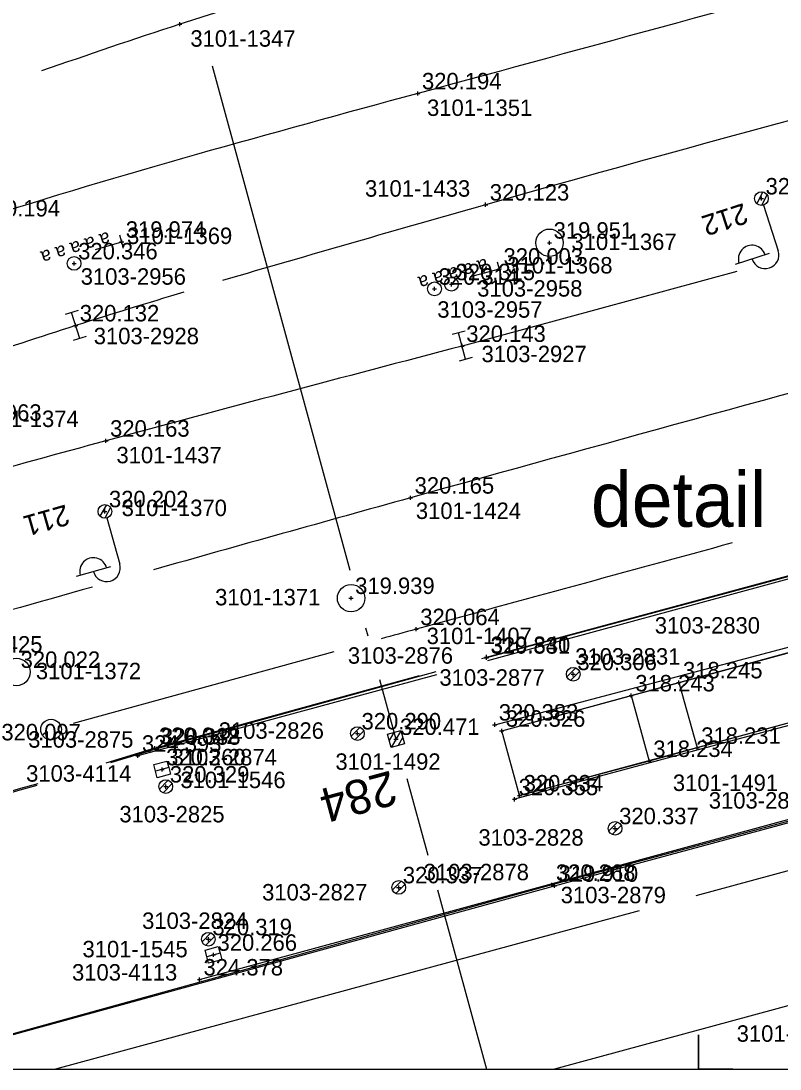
# Model space of a CAD drawing. Extents: x -821875 to -821475, y -1070280 to -1069975.
# Drawn here: x -821774.71 to -821747.03, y -1070250 to -1070211.76 of the extents above; entities that cross this region are included whole.
import ezdxf

# ---------------------------------------------------------------- set-up
doc = ezdxf.new("R2010")
doc.units = 0
for name, color, linetype in [('Vrstva 1', 7, 'Continuous'), ('Vrstva 11', 7, 'Continuous'), ('Vrstva 14', 7, 'Continuous'), ('Vrstva 17', 7, 'Continuous'), ('Vrstva 18', 7, 'Continuous'), ('Vrstva 25', 7, 'Continuous'), ('Vrstva 28', 7, 'Continuous'), ('Vrstva 3', 7, 'Continuous'), ('Vrstva 36', 7, 'Continuous'), ('Vrstva 43', 7, 'Continuous'), ('Vrstva 51', 7, 'Continuous'), ('Vrstva 6', 7, 'Continuous'), ('Vrstva 60', 7, 'Continuous'), ('Vrstva 61', 7, 'Continuous'), ('Vrstva 7', 7, 'Continuous')]:
    doc.layers.add(name, color=color, linetype=linetype)

# ---------------------------------------------------------------- blocks, each defined once
blk = doc.blocks.new('BOD')
at = {"layer": 'Vrstva 3'}
for p, q in [((-0.15, 0), (0.15, 0)), ((0, -0.15), (0, 0.15))]:
    blk.add_line(p, q, dxfattribs=at)

msp = doc.modelspace()

# ---------------------------------------------------------------- linework, layer by layer
at = {"layer": 'Vrstva 1'}
msp.add_line((-821763.295, -1070234.772), (-821772.807, -1070237.389), dxfattribs=at)
msp.add_lwpolyline([(-821500, -1070000), (-821850, -1070000), (-821850, -1070250), (-821500, -1070250)], close=True, dxfattribs=at)
msp.add_lwpolyline([(-821500, -1070000), (-821850, -1070000), (-821850, -1070250), (-821500, -1070250)], close=True, dxfattribs=at)
for points in [[(-821748.606, -1070220.895), (-821758.62, -1070223.618)], [(-821740.322, -1070241.025), (-821750.102, -1070243.674)], [(-821752.166, -1070244.233), (-821773.458, -1070250)], [(-821739.032, -1070245.599), (-821755.257, -1070250)], [(-821750, -1070250), (-821750, -1070248.75), (-821750, -1070250)], [(-821751.25, -1070250), (-821750, -1070250)], [(-821750, -1070250), (-821748.75, -1070250), (-821750, -1070250)]]:
    msp.add_lwpolyline(points, dxfattribs=at)
for points in [[(-821710.276, -1070200.761), (-821741.264, -1070209.238), (-821760.235, -1070214.402), (-821776.338, -1070219.041), (-821794.464, -1070225.772), (-821811.866, -1070233.595), (-821823.5, -1070239.204)], [(-821742.542, -1070204.561), (-821755.391, -1070207.946), (-821768.915, -1070211.875), (-821773.964, -1070213.578)], [(-821709.336, -1070205.287), (-821731.872, -1070211.395), (-821757.763, -1070218.461), (-821767.367, -1070221.229)], [(-821705.268, -1070214.096), (-821739.917, -1070223.49), (-821760.504, -1070229.155), (-821769.875, -1070231.779)], [(-821768.767, -1070221.652), (-821772.719, -1070222.87), (-821780.508, -1070225.552), (-821790.618, -1070229.47), (-821802.014, -1070234.586)], [(-821758.62, -1070223.618), (-821771.612, -1070227.076), (-821781.946, -1070229.982), (-821793.276, -1070233.523), (-821801.308, -1070236.276)], [(-821748.77, -1070230.804), (-821760.298, -1070233.952), (-821761.578, -1070234.302)], [(-821772.109, -1070232.413), (-821778.099, -1070234.122), (-821792.905, -1070238.705), (-821809.105, -1070244.426), (-821819.525, -1070248.451)]]:
    msp.add_spline(points, degree=3, dxfattribs=at)
at = {"layer": 'Vrstva 11'}
for p, q in [((-821767.74, -1070213.4), (-821762.717, -1070231.799)), ((-821762.144, -1070233.898), (-821762.063, -1070234.195)), ((-821761.629, -1070235.783), (-821761.035, -1070237.959)), ((-821761.113, -1070237.721), (-821761.28, -1070238.011)), ((-821760.859, -1070237.654), (-821761.21, -1070238.265)), ((-821760.79, -1070237.91), (-821760.954, -1070238.196)), ((-821761.035, -1070237.959), (-821761.029, -1070237.982)), ((-821760.639, -1070239.403), (-821759.871, -1070242.2)), ((-821759.525, -1070243.46), (-821757.731, -1070250))]:
    msp.add_line(p, q, dxfattribs=at)
msp.add_lwpolyline([(-821760.729, -1070238.135), (-821761.211, -1070238.265), (-821761.341, -1070237.783), (-821760.859, -1070237.653)], close=True, dxfattribs=at)
msp.add_lwpolyline([(-821760.729, -1070238.135), (-821761.211, -1070238.265), (-821761.341, -1070237.783), (-821760.859, -1070237.653), (-821760.729, -1070238.135)], dxfattribs=at)
at = {"layer": 'Vrstva 14'}
for p, q in [((-821664.962, -1070209.896), (-821757.694, -1070235.105)), ((-821768.204, -1070246.736), (-821665.012, -1070218.658)), ((-821729.033, -1070227.268), (-821757.732, -1070234.994)), ((-821757.728, -1070234.967), (-821729.11, -1070227.249)), ((-821757.901, -1070235.014), (-821757.728, -1070234.967)), ((-821757.732, -1070234.994), (-821757.743, -1070234.997)), ((-821759.554, -1070235.61), (-821770.449, -1070238.572)), ((-821759.581, -1070235.505), (-821769.755, -1070238.316)), ((-821769.828, -1070238.29), (-821760.173, -1070235.639)), ((-821727.507, -1070235.797), (-821755.35, -1070243.283)), ((-821755.252, -1070243.318), (-821727.465, -1070235.8)), ((-821769.828, -1070238.29), (-821771.614, -1070238.834)), ((-821769.755, -1070238.316), (-821771.448, -1070238.832)), ((-821755.35, -1070243.283), (-821779.667, -1070250)), ((-821779.579, -1070250), (-821755.252, -1070243.318))]:
    msp.add_line(p, q, dxfattribs=at)
for points in [[(-821774.103, -1070239.592), (-821793.856, -1070245.607), (-821805.756, -1070250)], [(-821774.135, -1070239.651), (-821793.856, -1070245.665), (-821805.638, -1070250)]]:
    msp.add_spline(points, degree=3, dxfattribs=at)
at = {"layer": 'Vrstva 17'}
msp.add_lwpolyline([(-821757.433, -1070237.436), (-821746.637, -1070234.581), (-821745.884, -1070237.251), (-821756.709, -1070240.158)], dxfattribs=at)
at = {"layer": 'Vrstva 18'}
for points in [[(-821757.178, -1070237.66), (-821746.762, -1070234.831), (-821746.658, -1070234.777), (-821746.001, -1070234.589)], [(-821756.527, -1070240.021), (-821746.098, -1070237.192), (-821746, -1070237.183), (-821745.337, -1070237.015)]]:
    msp.add_lwpolyline(points, dxfattribs=at)
at = {"layer": 'Vrstva 25'}
for p, q in [((-821747.656, -1070217.992), (-821747.875, -1070218.419)), ((-821747.498, -1070218.094), (-821747.698, -1070218.486)), ((-821747.626, -1070218.476), (-821747.091, -1070220.141)), ((-821747.424, -1070220.248), (-821748.663, -1070220.646)), ((-821771.597, -1070229.409), (-821771.831, -1070229.827)), ((-821771.443, -1070229.516), (-821771.658, -1070229.901)), ((-821771.585, -1070229.893), (-821771.107, -1070231.576)), ((-821771.443, -1070231.672), (-821772.695, -1070232.027))]:
    msp.add_line(p, q, dxfattribs=at)
for centre in [(-821747.703, -1070218.237), (-821747.703, -1070218.237), (-821771.653, -1070229.652), (-821771.653, -1070229.652)]:
    msp.add_circle(centre, 0.25, dxfattribs=at)
for centre, start, end in [((-821748.045, -1070220.441), 17.103, 198.5081), ((-821747.567, -1070220.294), 197.8055, 17.8055), ((-821772.071, -1070231.843), 15.1393, 196.5445), ((-821771.588, -1070231.713), 195.8419, 15.8419)]:
    msp.add_arc(centre, 0.5, start, end, dxfattribs=at)
at = {"layer": 'Vrstva 28'}
for p, q in [((-821772.801, -1070220.606), (-821772.751, -1070220.606)), ((-821759.035, -1070221.366), (-821758.985, -1070221.366)), ((-821759.654, -1070221.532), (-821759.604, -1070221.532))]:
    msp.add_line(p, q, dxfattribs=at)
for centre in [(-821772.776, -1070220.606), (-821759.629, -1070221.532), (-821759.01, -1070221.366)]:
    msp.add_circle(centre, 0.25, dxfattribs=at)
at = {"layer": 'Vrstva 3'}
for p, q in [((-821772.629, -1070222.318), (-821773.106, -1070222.467)), ((-821772.57, -1070223.347), (-821772.868, -1070222.393)), ((-821772.332, -1070223.273), (-821772.809, -1070223.422)), ((-821758.507, -1070223.071), (-821758.99, -1070223.199)), ((-821758.492, -1070224.101), (-821758.748, -1070223.135)), ((-821758.25, -1070224.037), (-821758.733, -1070224.165))]:
    msp.add_line(p, q, dxfattribs=at)
at = {"layer": 'Vrstva 36'}
for p, q in [((-821754.798, -1070235.688), (-821754.476, -1070235.365)), ((-821754.668, -1070235.823), (-821754.341, -1070235.496)), ((-821762.67, -1070237.85), (-821762.346, -1070237.527)), ((-821762.54, -1070237.985), (-821762.212, -1070237.658)), ((-821769.662, -1070239.787), (-821769.34, -1070239.464)), ((-821769.532, -1070239.922), (-821769.205, -1070239.594)), ((-821753.274, -1070241.309), (-821752.95, -1070240.986)), ((-821753.144, -1070241.444), (-821752.816, -1070241.116)), ((-821761.164, -1070243.465), (-821760.842, -1070243.142)), ((-821761.034, -1070243.6), (-821760.707, -1070243.272)), ((-821768.108, -1070245.358), (-821767.786, -1070245.035)), ((-821767.978, -1070245.493), (-821767.651, -1070245.166))]:
    msp.add_line(p, q, dxfattribs=at)
for centre in [(-821754.568, -1070235.596), (-821762.439, -1070237.758), (-821769.432, -1070239.695), (-821753.043, -1070241.217), (-821760.934, -1070243.373), (-821767.878, -1070245.266)]:
    msp.add_circle(centre, 0.25, dxfattribs=at)
at = {"layer": 'Vrstva 43'}
for points in [[(-821769.324, -1070239.002), (-821769.259, -1070239.243), (-821769.741, -1070239.373), (-821769.871, -1070238.891), (-821769.389, -1070238.761), (-821769.324, -1070239.002), (-821769.806, -1070239.132)], [(-821767.452, -1070245.77), (-821767.387, -1070246.011), (-821767.869, -1070246.141), (-821767.999, -1070245.659), (-821767.517, -1070245.529), (-821767.452, -1070245.77), (-821767.934, -1070245.9)]]:
    msp.add_lwpolyline(points, dxfattribs=at)
for centre in [(-821755.433, -1070219.85), (-821762.673, -1070232.816), (-821774.875, -1070235.512)]:
    msp.add_circle(centre, 0.5, dxfattribs=at)
at = {"layer": 'Vrstva 51'}
for points in [[(-821750.714, -1070235.894), (-821746.005, -1070234.604), (-821745.854, -1070235.153)], [(-821752.454, -1070236.371), (-821750.714, -1070235.894), (-821750.05, -1070238.283), (-821751.798, -1070238.763)], [(-821756.527, -1070240.021), (-821757.178, -1070237.66), (-821752.454, -1070236.371), (-821751.798, -1070238.763), (-821756.527, -1070240.021)], [(-821745.448, -1070236.63), (-821745.346, -1070237.001), (-821750.05, -1070238.283)]]:
    msp.add_lwpolyline(points, dxfattribs=at)
at = {"layer": 'Vrstva 6'}
for p, q in [((-821771.989, -1070220.098), (-821771.039, -1070219.818)), ((-821770.969, -1070220.057), (-821771.109, -1070219.579)), ((-821757.195, -1070221.041), (-821757.327, -1070220.559)), ((-821758.216, -1070221.061), (-821757.261, -1070220.8))]:
    msp.add_line(p, q, dxfattribs=at)
at = {"layer": 'Vrstva 7'}
msp.add_circle((-821773.615, -1070237.614), 0.375, dxfattribs=at)

# ---------------------------------------------------------------- block references
at = {"layer": 'Vrstva 60', "xscale": 0.5, "yscale": 0.5}
for p in [(-821768.915, -1070211.875), (-821760.235, -1070214.402), (-821757.763, -1070218.461), (-821747.703, -1070218.237), (-821771.039, -1070219.818), (-821755.433, -1070219.85), (-821772.776, -1070220.606), (-821757.261, -1070220.8), (-821759.629, -1070221.532), (-821759.01, -1070221.366), (-821772.719, -1070222.87), (-821758.62, -1070223.618), (-821771.612, -1070227.076), (-821760.504, -1070229.155), (-821771.653, -1070229.652), (-821762.673, -1070232.816), (-821760.298, -1070233.952), (-821757.732, -1070234.994), (-821757.728, -1070234.967), (-821754.568, -1070235.596), (-821750.714, -1070235.894), (-821752.454, -1070236.371), (-821757.433, -1070237.436), (-821762.439, -1070237.758), (-821761.035, -1070237.959), (-821757.178, -1070237.66), (-821769.828, -1070238.29), (-821769.755, -1070238.316), (-821750.05, -1070238.283), (-821770.449, -1070238.572), (-821751.798, -1070238.763), (-821769.565, -1070239.067), (-821769.432, -1070239.695), (-821756.709, -1070240.158), (-821756.527, -1070240.021), (-821753.043, -1070241.217), (-821755.35, -1070243.283), (-821755.252, -1070243.318), (-821760.934, -1070243.373), (-821767.878, -1070245.266), (-821767.693, -1070245.835), (-821768.204, -1070246.736)]:
    msp.add_blockref('BOD', p, dxfattribs=at)

# ---------------------------------------------------------------- texts
at = {"layer": 'Vrstva 1'}
msp.add_text('detail 1', height=2, dxfattribs=at).set_placement((-821753.921, -1070230.216))
at = {"layer": 'Vrstva 11'}
msp.add_text('284', height=1.25, rotation=195.0948, dxfattribs=at).set_placement((-821761.22, -1070239.099))
at = {"layer": 'Vrstva 25'}
for s, rotation, p in [('212', 197.8054, (-821748.351, -1070218.393)), ('211', 195.8419, (-821773.077, -1070229.394))]:
    msp.add_text(s, height=0.75, rotation=rotation, dxfattribs=at).set_placement(p)
at = {"layer": 'Vrstva 6'}
for rotation, p in [(196.417, (-821771.18, -1070219.338)), (195.2878, (-821757.393, -1070220.317))]:
    msp.add_text('  a a a a a', height=0.5, rotation=rotation, dxfattribs=at).set_placement(p)
at = {"layer": 'Vrstva 60'}
for s, p in [('3101-1347', (-821768.533, -1070212.696)), ('3101-1351', (-821759.9, -1070215.223)), ('3101-1433', (-821762.163, -1070218.169)), ('3101-1369', (-821770.843, -1070219.897)), ('3101-1367', (-821754.633, -1070220.114)), ('3101-1368', (-821756.972, -1070220.972)), ('3103-2956', (-821772.533, -1070221.381)), ('3103-2958', (-821758.07, -1070221.816)), ('3103-2957', (-821759.526, -1070222.585)), ('3103-2928', (-821772.058, -1070223.552)), ('3103-2927', (-821757.913, -1070224.207)), ('3101-1374', (-821776.443, -1070226.574)), ('3101-1437', (-821771.23, -1070227.897)), ('3101-1370', (-821771.039, -1070229.824)), ('3101-1424', (-821760.308, -1070229.929)), ('3101-1371', (-821767.631, -1070233.081)), ('3103-2830', (-821751.593, -1070234.111)), ('3101-1407', (-821759.915, -1070234.495)), ('3101-1425', (-821777.764, -1070234.804)), ('3103-2876', (-821762.788, -1070235.21)), ('3103-2831', (-821754.495, -1070235.244)), ('3101-1372', (-821774.168, -1070235.777)), ('3103-2877', (-821759.449, -1070236.013)), ('3103-2826', (-821767.499, -1070237.949)), ('3103-2875', (-821774.448, -1070238.274)), ('3103-2874', (-821769.216, -1070238.922)), ('3101-1492', (-821763.244, -1070239.082)), ('3103-4114', (-821774.525, -1070239.514)), ('3101-1546', (-821768.897, -1070239.75)), ('3101-1491', (-821750.933, -1070239.854)), ('3103-2829', (-821749.623, -1070240.498)), ('3103-2825', (-821771.123, -1070241)), ('3103-2828', (-821758.026, -1070241.849)), ('3103-2878', (-821760.022, -1070243.112)), ('3103-2827', (-821765.917, -1070243.849)), ('3103-2879', (-821755.024, -1070243.95)), ('3103-2824', (-821770.294, -1070244.888)), ('3101-1545', (-821772.468, -1070245.923)), ('3103-4113', (-821772.85, -1070246.772)), ('3101-1476', (-821748.606, -1070249.005))]:
    msp.add_text(s, height=0.6, dxfattribs=at).set_placement(p)
at = {"layer": 'Vrstva 61'}
for s, p in [('320.194', (-821760.085, -1070214.252)), ('320.311', (-821747.553, -1070218.087)), ('320.123', (-821757.613, -1070218.311)), ('320.194', (-821776.188, -1070218.891)), ('319.974', (-821770.889, -1070219.668)), ('319.951', (-821755.283, -1070219.7)), ('320.346', (-821772.626, -1070220.456)), ('320.003', (-821757.111, -1070220.65)), ('320.315', (-821758.86, -1070221.216)), ('320.314', (-821759.479, -1070221.382)), ('320.132', (-821772.569, -1070222.72)), ('320.143', (-821758.47, -1070223.468)), ('319.963', (-821776.861, -1070226.345)), ('320.163', (-821771.462, -1070226.926)), ('320.165', (-821760.354, -1070229.005)), ('320.202', (-821771.503, -1070229.502)), ('319.939', (-821762.523, -1070232.666)), ('320.064', (-821760.148, -1070233.802)), ('320.331', (-821757.582, -1070234.844)), ('319.840', (-821757.578, -1070234.817)), ('320.022', (-821774.725, -1070235.362)), ('320.306', (-821754.418, -1070235.446)), ('318.245', (-821750.564, -1070235.744)), ('318.243', (-821752.304, -1070236.221)), ('320.383', (-821757.283, -1070237.286)), ('320.290', (-821762.289, -1070237.608)), ('320.326', (-821757.028, -1070237.51)), ('320.097', (-821775.427, -1070238.007)), ('320.042', (-821769.678, -1070238.14)), ('320.471', (-821760.885, -1070237.809)), ('318.231', (-821749.9, -1070238.133)), ('324.393', (-821770.299, -1070238.422)), ('320.338', (-821769.605, -1070238.166)), ('320.260', (-821769.415, -1070238.917)), ('318.234', (-821751.648, -1070238.613)), ('320.329', (-821769.282, -1070239.545)), ('320.355', (-821756.559, -1070240.008)), ('320.334', (-821756.377, -1070239.871)), ('320.337', (-821752.893, -1070241.067)), ('320.337', (-821760.784, -1070243.223)), ('320.268', (-821755.2, -1070243.133)), ('319.910', (-821755.102, -1070243.168)), ('320.319', (-821767.728, -1070245.116)), ('320.266', (-821767.543, -1070245.685)), ('324.378', (-821768.054, -1070246.586))]:
    msp.add_text(s, height=0.6, dxfattribs=at).set_placement(p)

doc.saveas('drawing.dxf')
